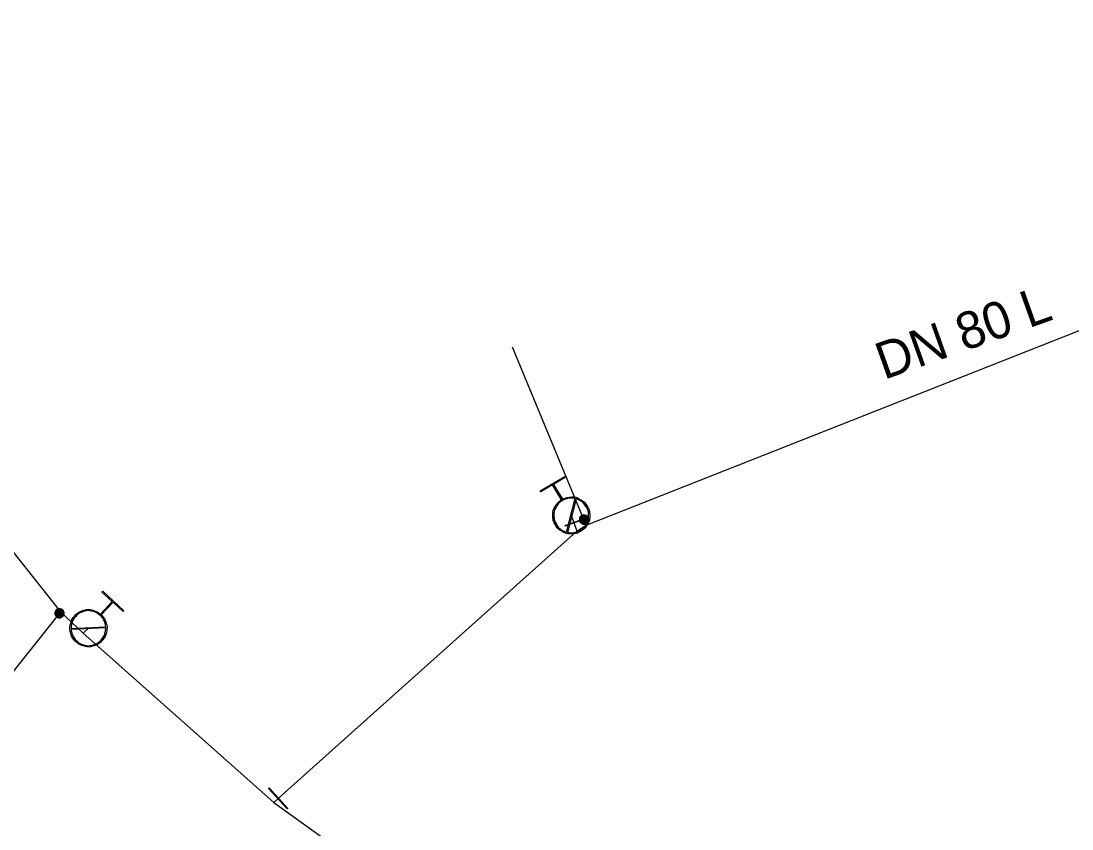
# Model space of a CAD drawing. Extents: x -832382 to -831581, y -1074670 to -1074251.
# Drawn here: x -831683.8 to -831626.9, y -1074480.2 to -1074436.4 of the extents above; entities that cross this region are included whole.
import ezdxf

# ---------------------------------------------------------------- set-up
doc = ezdxf.new("R2010")
doc.units = 0
for name, color, linetype in [('Hyd-odbočka', 7, 'Continuous'), ('Hyd-šoupě', 7, 'Continuous'), ('Hydrant', 7, 'Continuous'), ('Přípojka vodovodu', 7, 'Continuous'), ('Přípojkový uzávěr', 7, 'Continuous'), ('Roz-řad', 7, 'Continuous'), ('Roz-řad-popis základní', 7, 'Continuous'), ('Řad-šoupě', 7, 'Continuous')]:
    doc.layers.add(name, color=color, linetype=linetype)

msp = doc.modelspace()

# ---------------------------------------------------------------- linework, layer by layer
at = {"layer": 'Hyd-odbočka'}
for p, q in [((-831653.98, -1074463.23), (-831653.84, -1074463.62)), ((-831653.84, -1074463.62), (-831653.675, -1074464.08)), ((-831680.14, -1074469.34), (-831680.42, -1074469.611))]:
    msp.add_line(p, q, dxfattribs=at)
at = {"layer": 'Hyd-šoupě'}
msp.add_lwpolyline([(-831654.316, -1074463.774), (-831653.375, -1074463.436), (-831653.364, -1074463.466), (-831654.305, -1074463.804), (-831654.316, -1074463.774)], dxfattribs=at)
at = {"layer": 'Hydrant'}
for points in [[(-831654.514, -1074462.384), (-831654.989, -1074461.576), (-831655.636, -1074461.956), (-831655.667, -1074461.902), (-831654.32, -1074461.11), (-831654.289, -1074461.164), (-831654.935, -1074461.544), (-831654.46, -1074462.352)], [(-831654.245, -1074464.131), (-831653.774, -1074462.313)], [(-831653.715, -1074462.329), (-831654.185, -1074464.148)], [(-831679.487, -1074468.582), (-831678.852, -1074467.892), (-831679.405, -1074467.385), (-831679.362, -1074467.339), (-831678.212, -1074468.396), (-831678.254, -1074468.442), (-831678.806, -1074467.934), (-831679.441, -1074468.625)], [(-831681.08, -1074469.35), (-831679.203, -1074469.27)], [(-831679.2, -1074469.33), (-831681.078, -1074469.412)]]:
    msp.add_lwpolyline(points, dxfattribs=at)
for points in [[(-831654.46, -1074462.352), (-831654.252, -1074462.239), (-831653.997, -1074462.23), (-831653.727, -1074462.22), (-831653.489, -1074462.359), (-831653.251, -1074462.498), (-831653.118, -1074462.723), (-831652.986, -1074462.947), (-831652.979, -1074463.219), (-831652.972, -1074463.491), (-831653.111, -1074463.726), (-831653.249, -1074463.96), (-831653.473, -1074464.092), (-831653.697, -1074464.224), (-831653.969, -1074464.231), (-831654.241, -1074464.238), (-831654.476, -1074464.099), (-831654.71, -1074463.961), (-831654.842, -1074463.737), (-831654.975, -1074463.511), (-831654.98, -1074463.236), (-831654.986, -1074462.96), (-831654.846, -1074462.729), (-831654.715, -1074462.511), (-831654.514, -1074462.384)], [(-831653.774, -1074462.313), (-831653.883, -1074462.289), (-831653.996, -1074462.293), (-831654.251, -1074462.302), (-831654.455, -1074462.422), (-831654.659, -1074462.542), (-831654.791, -1074462.76), (-831654.923, -1074462.978), (-831654.918, -1074463.236), (-831654.913, -1074463.493), (-831654.788, -1074463.705), (-831654.664, -1074463.916), (-831654.444, -1074464.044), (-831654.349, -1074464.102), (-831654.245, -1074464.131)], [(-831654.185, -1074464.148), (-831654.081, -1074464.171), (-831653.971, -1074464.167), (-831653.715, -1074464.162), (-831653.505, -1074464.038), (-831653.294, -1074463.914), (-831653.164, -1074463.694), (-831653.035, -1074463.474), (-831653.041, -1074463.22), (-831653.048, -1074462.965), (-831653.172, -1074462.755), (-831653.297, -1074462.543), (-831653.52, -1074462.413), (-831653.616, -1074462.359), (-831653.715, -1074462.329)], [(-831679.441, -1074468.625), (-831679.272, -1074468.79), (-831679.188, -1074469.031), (-831679.1, -1074469.288), (-831679.163, -1074469.556), (-831679.226, -1074469.824), (-831679.404, -1074470.016), (-831679.579, -1074470.208), (-831679.838, -1074470.294), (-831680.096, -1074470.38), (-831680.36, -1074470.316), (-831680.625, -1074470.252), (-831680.816, -1074470.076), (-831681.008, -1074469.901), (-831681.094, -1074469.642), (-831681.18, -1074469.384), (-831681.116, -1074469.12), (-831681.052, -1074468.855), (-831680.876, -1074468.664), (-831680.699, -1074468.471), (-831680.438, -1074468.385), (-831680.176, -1074468.299), (-831679.913, -1074468.366), (-831679.667, -1074468.427), (-831679.487, -1074468.582)], [(-831679.203, -1074469.27), (-831679.212, -1074469.158), (-831679.248, -1074469.051), (-831679.332, -1074468.809), (-831679.506, -1074468.65), (-831679.68, -1074468.49), (-831679.927, -1074468.427), (-831680.175, -1074468.364), (-831680.419, -1074468.444), (-831680.664, -1074468.525), (-831680.83, -1074468.706), (-831680.996, -1074468.886), (-831681.054, -1074469.134), (-831681.081, -1074469.242), (-831681.08, -1074469.35)], [(-831681.078, -1074469.412), (-831681.07, -1074469.518), (-831681.033, -1074469.623), (-831680.954, -1074469.865), (-831680.774, -1074470.03), (-831680.594, -1074470.196), (-831680.346, -1074470.256), (-831680.097, -1074470.315), (-831679.856, -1074470.235), (-831679.615, -1074470.154), (-831679.45, -1074469.974), (-831679.283, -1074469.793), (-831679.225, -1074469.542), (-831679.2, -1074469.434), (-831679.2, -1074469.33)]]:
    msp.add_open_spline(points, degree=3, dxfattribs=at)
at = {"layer": 'Přípojka vodovodu'}
for points in [[(-831653.163, -1074463.755), (-831653.29, -1074463.45), (-831657.171, -1074454.115)], [(-831681.645, -1074468.448), (-831681.71, -1074468.53), (-831689.553, -1074478.367), (-831687.925, -1074479.696)]]:
    msp.add_lwpolyline(points, dxfattribs=at)
at = {"layer": 'Přípojkový uzávěr'}
for points in [[(-831653.29, -1074463.2), (-831653.227, -1074463.2), (-831653.167, -1074463.232), (-831653.108, -1074463.264), (-831653.074, -1074463.325), (-831653.04, -1074463.385), (-831653.04, -1074463.45), (-831653.04, -1074463.515), (-831653.073, -1074463.575), (-831653.106, -1074463.634), (-831653.165, -1074463.667), (-831653.225, -1074463.7), (-831653.29, -1074463.7), (-831653.355, -1074463.7), (-831653.415, -1074463.667), (-831653.474, -1074463.634), (-831653.507, -1074463.575), (-831653.54, -1074463.515), (-831653.54, -1074463.45), (-831653.54, -1074463.385), (-831653.506, -1074463.325), (-831653.473, -1074463.264), (-831653.413, -1074463.232), (-831653.353, -1074463.2), (-831653.29, -1074463.2)], [(-831653.29, -1074463.223), (-831653.347, -1074463.223), (-831653.402, -1074463.253), (-831653.456, -1074463.282), (-831653.486, -1074463.336), (-831653.517, -1074463.391), (-831653.517, -1074463.45), (-831653.517, -1074463.509), (-831653.487, -1074463.563), (-831653.457, -1074463.617), (-831653.403, -1074463.647), (-831653.349, -1074463.677), (-831653.29, -1074463.677), (-831653.231, -1074463.677), (-831653.177, -1074463.647), (-831653.123, -1074463.617), (-831653.093, -1074463.563), (-831653.063, -1074463.509), (-831653.063, -1074463.45), (-831653.063, -1074463.391), (-831653.094, -1074463.336), (-831653.125, -1074463.282), (-831653.179, -1074463.253), (-831653.233, -1074463.223), (-831653.29, -1074463.223)], [(-831653.29, -1074463.241), (-831653.237, -1074463.241), (-831653.187, -1074463.268), (-831653.137, -1074463.294), (-831653.109, -1074463.345), (-831653.081, -1074463.395), (-831653.081, -1074463.45), (-831653.081, -1074463.505), (-831653.108, -1074463.554), (-831653.135, -1074463.604), (-831653.186, -1074463.632), (-831653.236, -1074463.659), (-831653.29, -1074463.659), (-831653.344, -1074463.659), (-831653.394, -1074463.632), (-831653.445, -1074463.604), (-831653.472, -1074463.554), (-831653.499, -1074463.505), (-831653.499, -1074463.45), (-831653.499, -1074463.395), (-831653.471, -1074463.345), (-831653.443, -1074463.294), (-831653.393, -1074463.268), (-831653.343, -1074463.241), (-831653.29, -1074463.241)], [(-831653.29, -1074463.262), (-831653.369, -1074463.262), (-831653.423, -1074463.317), (-831653.478, -1074463.372), (-831653.478, -1074463.45), (-831653.478, -1074463.528), (-831653.423, -1074463.583), (-831653.368, -1074463.637), (-831653.29, -1074463.637), (-831653.212, -1074463.637), (-831653.157, -1074463.583), (-831653.103, -1074463.528), (-831653.103, -1074463.45), (-831653.103, -1074463.372), (-831653.157, -1074463.317), (-831653.212, -1074463.262), (-831653.29, -1074463.262)], [(-831653.29, -1074463.285), (-831653.222, -1074463.285), (-831653.174, -1074463.333), (-831653.126, -1074463.381), (-831653.126, -1074463.45), (-831653.126, -1074463.518), (-831653.174, -1074463.566), (-831653.222, -1074463.614), (-831653.29, -1074463.614), (-831653.359, -1074463.614), (-831653.407, -1074463.566), (-831653.455, -1074463.518), (-831653.455, -1074463.45), (-831653.455, -1074463.381), (-831653.407, -1074463.333), (-831653.359, -1074463.285), (-831653.29, -1074463.285)], [(-831653.29, -1074463.305), (-831653.351, -1074463.305), (-831653.393, -1074463.347), (-831653.435, -1074463.39), (-831653.435, -1074463.45), (-831653.435, -1074463.509), (-831653.393, -1074463.552), (-831653.351, -1074463.594), (-831653.29, -1074463.594), (-831653.231, -1074463.594), (-831653.188, -1074463.552), (-831653.146, -1074463.509), (-831653.146, -1074463.45), (-831653.146, -1074463.39), (-831653.188, -1074463.347), (-831653.23, -1074463.305), (-831653.29, -1074463.305)], [(-831653.29, -1074463.325), (-831653.238, -1074463.325), (-831653.201, -1074463.362), (-831653.165, -1074463.398), (-831653.165, -1074463.45), (-831653.165, -1074463.502), (-831653.202, -1074463.539), (-831653.238, -1074463.575), (-831653.29, -1074463.575), (-831653.342, -1074463.575), (-831653.378, -1074463.539), (-831653.415, -1074463.502), (-831653.415, -1074463.45), (-831653.415, -1074463.398), (-831653.379, -1074463.362), (-831653.342, -1074463.325), (-831653.29, -1074463.325)], [(-831653.29, -1074463.348), (-831653.332, -1074463.348), (-831653.362, -1074463.378), (-831653.392, -1074463.408), (-831653.392, -1074463.45), (-831653.392, -1074463.492), (-831653.362, -1074463.522), (-831653.332, -1074463.551), (-831653.29, -1074463.551), (-831653.248, -1074463.551), (-831653.218, -1074463.522), (-831653.189, -1074463.492), (-831653.189, -1074463.45), (-831653.189, -1074463.408), (-831653.218, -1074463.378), (-831653.248, -1074463.348), (-831653.29, -1074463.348)], [(-831653.29, -1074463.366), (-831653.255, -1074463.366), (-831653.231, -1074463.39), (-831653.206, -1074463.415), (-831653.206, -1074463.45), (-831653.206, -1074463.485), (-831653.231, -1074463.509), (-831653.255, -1074463.534), (-831653.29, -1074463.534), (-831653.325, -1074463.534), (-831653.35, -1074463.509), (-831653.374, -1074463.485), (-831653.374, -1074463.45), (-831653.374, -1074463.415), (-831653.35, -1074463.39), (-831653.325, -1074463.366), (-831653.29, -1074463.366)], [(-831653.29, -1074463.387), (-831653.316, -1074463.387), (-831653.334, -1074463.406), (-831653.353, -1074463.424), (-831653.353, -1074463.45), (-831653.353, -1074463.476), (-831653.334, -1074463.494), (-831653.316, -1074463.512), (-831653.29, -1074463.512), (-831653.264, -1074463.512), (-831653.246, -1074463.494), (-831653.228, -1074463.476), (-831653.228, -1074463.45), (-831653.228, -1074463.424), (-831653.246, -1074463.406), (-831653.264, -1074463.387), (-831653.29, -1074463.387)], [(-831653.29, -1074463.411), (-831653.274, -1074463.411), (-831653.262, -1074463.422), (-831653.251, -1074463.433), (-831653.251, -1074463.45), (-831653.251, -1074463.466), (-831653.262, -1074463.478), (-831653.274, -1074463.489), (-831653.29, -1074463.489), (-831653.306, -1074463.489), (-831653.318, -1074463.478), (-831653.329, -1074463.466), (-831653.329, -1074463.45), (-831653.329, -1074463.433), (-831653.318, -1074463.422), (-831653.306, -1074463.411), (-831653.29, -1074463.411)], [(-831653.29, -1074463.427), (-831653.3, -1074463.427), (-831653.307, -1074463.433), (-831653.314, -1074463.44), (-831653.314, -1074463.45), (-831653.314, -1074463.46), (-831653.307, -1074463.467), (-831653.3, -1074463.473), (-831653.29, -1074463.473), (-831653.28, -1074463.473), (-831653.274, -1074463.467), (-831653.267, -1074463.46), (-831653.267, -1074463.45), (-831653.267, -1074463.44), (-831653.274, -1074463.433), (-831653.28, -1074463.427), (-831653.29, -1074463.427)], [(-831681.71, -1074468.28), (-831681.647, -1074468.28), (-831681.587, -1074468.312), (-831681.528, -1074468.344), (-831681.494, -1074468.405), (-831681.46, -1074468.465), (-831681.46, -1074468.53), (-831681.46, -1074468.595), (-831681.493, -1074468.655), (-831681.526, -1074468.714), (-831681.585, -1074468.747), (-831681.645, -1074468.78), (-831681.71, -1074468.78), (-831681.775, -1074468.78), (-831681.835, -1074468.747), (-831681.894, -1074468.714), (-831681.927, -1074468.655), (-831681.96, -1074468.595), (-831681.96, -1074468.53), (-831681.96, -1074468.465), (-831681.926, -1074468.405), (-831681.893, -1074468.344), (-831681.833, -1074468.312), (-831681.773, -1074468.28), (-831681.71, -1074468.28)], [(-831681.71, -1074468.303), (-831681.767, -1074468.303), (-831681.822, -1074468.333), (-831681.876, -1074468.362), (-831681.906, -1074468.416), (-831681.937, -1074468.471), (-831681.937, -1074468.53), (-831681.937, -1074468.589), (-831681.907, -1074468.643), (-831681.877, -1074468.697), (-831681.823, -1074468.727), (-831681.769, -1074468.757), (-831681.71, -1074468.757), (-831681.651, -1074468.757), (-831681.597, -1074468.727), (-831681.543, -1074468.697), (-831681.513, -1074468.643), (-831681.483, -1074468.589), (-831681.483, -1074468.53), (-831681.483, -1074468.471), (-831681.514, -1074468.416), (-831681.545, -1074468.362), (-831681.599, -1074468.333), (-831681.653, -1074468.303), (-831681.71, -1074468.303)], [(-831681.71, -1074468.321), (-831681.657, -1074468.321), (-831681.607, -1074468.348), (-831681.557, -1074468.374), (-831681.529, -1074468.425), (-831681.501, -1074468.475), (-831681.501, -1074468.53), (-831681.501, -1074468.585), (-831681.528, -1074468.634), (-831681.555, -1074468.684), (-831681.606, -1074468.712), (-831681.656, -1074468.739), (-831681.71, -1074468.739), (-831681.764, -1074468.739), (-831681.814, -1074468.712), (-831681.865, -1074468.684), (-831681.892, -1074468.634), (-831681.919, -1074468.585), (-831681.919, -1074468.53), (-831681.919, -1074468.475), (-831681.891, -1074468.425), (-831681.863, -1074468.374), (-831681.813, -1074468.348), (-831681.763, -1074468.321), (-831681.71, -1074468.321)], [(-831681.71, -1074468.343), (-831681.789, -1074468.343), (-831681.843, -1074468.397), (-831681.897, -1074468.452), (-831681.897, -1074468.53), (-831681.897, -1074468.608), (-831681.843, -1074468.663), (-831681.788, -1074468.718), (-831681.71, -1074468.718), (-831681.632, -1074468.718), (-831681.577, -1074468.663), (-831681.522, -1074468.608), (-831681.522, -1074468.53), (-831681.522, -1074468.452), (-831681.577, -1074468.397), (-831681.632, -1074468.343), (-831681.71, -1074468.343)], [(-831681.71, -1074468.365), (-831681.642, -1074468.365), (-831681.594, -1074468.413), (-831681.546, -1074468.461), (-831681.546, -1074468.53), (-831681.546, -1074468.598), (-831681.594, -1074468.646), (-831681.642, -1074468.694), (-831681.71, -1074468.694), (-831681.779, -1074468.694), (-831681.827, -1074468.646), (-831681.875, -1074468.598), (-831681.875, -1074468.53), (-831681.875, -1074468.461), (-831681.827, -1074468.413), (-831681.779, -1074468.365), (-831681.71, -1074468.365)], [(-831681.71, -1074468.385), (-831681.771, -1074468.385), (-831681.813, -1074468.427), (-831681.855, -1074468.47), (-831681.855, -1074468.53), (-831681.855, -1074468.589), (-831681.813, -1074468.632), (-831681.771, -1074468.674), (-831681.71, -1074468.674), (-831681.651, -1074468.674), (-831681.608, -1074468.632), (-831681.566, -1074468.589), (-831681.566, -1074468.53), (-831681.566, -1074468.47), (-831681.608, -1074468.427), (-831681.65, -1074468.385), (-831681.71, -1074468.385)], [(-831681.71, -1074468.405), (-831681.658, -1074468.405), (-831681.621, -1074468.442), (-831681.585, -1074468.478), (-831681.585, -1074468.53), (-831681.585, -1074468.582), (-831681.622, -1074468.619), (-831681.658, -1074468.655), (-831681.71, -1074468.655), (-831681.762, -1074468.655), (-831681.798, -1074468.619), (-831681.835, -1074468.582), (-831681.835, -1074468.53), (-831681.835, -1074468.478), (-831681.799, -1074468.442), (-831681.762, -1074468.405), (-831681.71, -1074468.405)], [(-831681.71, -1074468.428), (-831681.752, -1074468.428), (-831681.782, -1074468.458), (-831681.812, -1074468.488), (-831681.812, -1074468.53), (-831681.812, -1074468.572), (-831681.782, -1074468.602), (-831681.752, -1074468.631), (-831681.71, -1074468.631), (-831681.668, -1074468.631), (-831681.638, -1074468.602), (-831681.609, -1074468.572), (-831681.609, -1074468.53), (-831681.609, -1074468.488), (-831681.638, -1074468.458), (-831681.668, -1074468.428), (-831681.71, -1074468.428)], [(-831681.71, -1074468.446), (-831681.675, -1074468.446), (-831681.651, -1074468.47), (-831681.626, -1074468.495), (-831681.626, -1074468.53), (-831681.626, -1074468.565), (-831681.651, -1074468.589), (-831681.675, -1074468.614), (-831681.71, -1074468.614), (-831681.745, -1074468.614), (-831681.77, -1074468.589), (-831681.794, -1074468.565), (-831681.794, -1074468.53), (-831681.794, -1074468.495), (-831681.77, -1074468.47), (-831681.745, -1074468.446), (-831681.71, -1074468.446)], [(-831681.71, -1074468.468), (-831681.736, -1074468.468), (-831681.754, -1074468.486), (-831681.772, -1074468.504), (-831681.772, -1074468.53), (-831681.772, -1074468.556), (-831681.754, -1074468.574), (-831681.736, -1074468.593), (-831681.71, -1074468.593), (-831681.684, -1074468.593), (-831681.666, -1074468.574), (-831681.647, -1074468.556), (-831681.647, -1074468.53), (-831681.647, -1074468.504), (-831681.666, -1074468.486), (-831681.684, -1074468.468), (-831681.71, -1074468.468)], [(-831681.71, -1074468.491), (-831681.694, -1074468.491), (-831681.682, -1074468.502), (-831681.671, -1074468.513), (-831681.671, -1074468.53), (-831681.671, -1074468.546), (-831681.682, -1074468.558), (-831681.694, -1074468.569), (-831681.71, -1074468.569), (-831681.726, -1074468.569), (-831681.738, -1074468.558), (-831681.749, -1074468.546), (-831681.749, -1074468.53), (-831681.749, -1074468.513), (-831681.738, -1074468.502), (-831681.726, -1074468.491), (-831681.71, -1074468.491)], [(-831681.71, -1074468.507), (-831681.72, -1074468.507), (-831681.727, -1074468.513), (-831681.734, -1074468.52), (-831681.734, -1074468.53), (-831681.734, -1074468.54), (-831681.727, -1074468.547), (-831681.72, -1074468.553), (-831681.71, -1074468.553), (-831681.7, -1074468.553), (-831681.694, -1074468.547), (-831681.687, -1074468.54), (-831681.687, -1074468.53), (-831681.687, -1074468.52), (-831681.694, -1074468.513), (-831681.7, -1074468.507), (-831681.71, -1074468.507)]]:
    msp.add_open_spline(points, degree=3, dxfattribs=at)
at = {"layer": 'Roz-řad'}
msp.add_line((-831669.86, -1074478.57), (-831670.1, -1074478.783), dxfattribs=at)
for points in [[(-831699.16, -1074436.43), (-831684.613, -1074464.713), (-831681.645, -1074468.448), (-831680.42, -1074469.611), (-831670.1, -1074478.783)], [(-831669.86, -1074478.57), (-831653.675, -1074464.08), (-831653.163, -1074463.755), (-831618.944, -1074450.246), (-831614.46, -1074448.41)], [(-831670.1, -1074478.783), (-831661.155, -1074485.222), (-831659.022, -1074486.757), (-831652.411, -1074491.516), (-831636.886, -1074502.691), (-831632.509, -1074505.888), (-831582.314, -1074542.549), (-831580.799, -1074543.602), (-831583.872, -1074547.6)]]:
    msp.add_lwpolyline(points, dxfattribs=at)
at = {"layer": 'Řad-šoupě'}
msp.add_lwpolyline([(-831670.348, -1074478), (-831669.337, -1074479.108), (-831669.372, -1074479.14), (-831670.383, -1074478.032), (-831670.348, -1074478)], dxfattribs=at)

# ---------------------------------------------------------------- texts
at = {"layer": 'Roz-řad-popis základní'}
msp.add_text('DN 80 L', height=2, rotation=19.6387, dxfattribs=at).set_placement((-831637.038, -1074455.889))

doc.saveas('drawing.dxf')
